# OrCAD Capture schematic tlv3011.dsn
size A
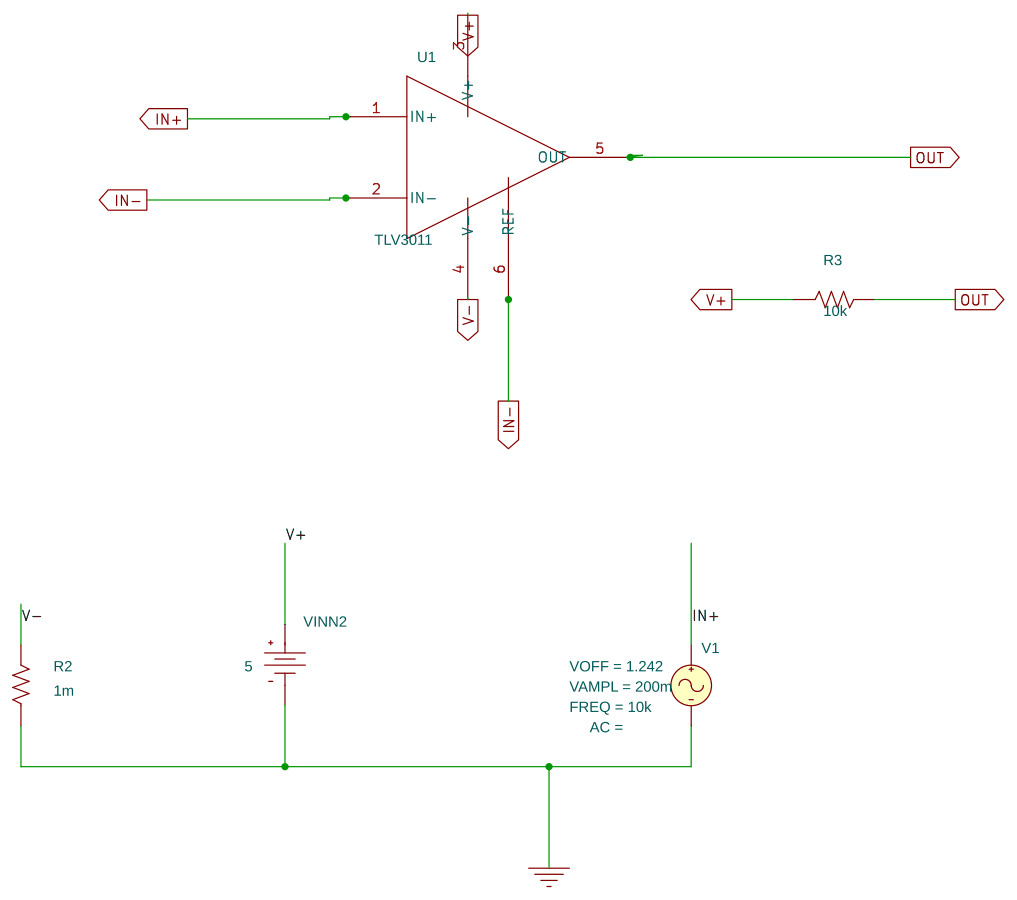
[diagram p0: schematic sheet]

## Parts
R2  1m  [AXRC05]
R3  10k  [AXRC05]
U1  TLV3011
V1  VSIN
VINN2  VDC

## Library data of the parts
R2 R3 = R
U1 = TLV3011_3
V1 = VSIN: FREQ: 10k; VAMPL: 200m; VOFF: 1.242
VINN2 = VDC: DC: 5

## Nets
0: R2.1 V1.2(-) VINN2.1(-)
IN+: U1.1(IN+) V1.1(+)
IN-: U1.2(IN-) U1.6(REF)
OUT: R3.2 U1.5(OUT)
V+: R3.1 U1.3(V+) VINN2.0(+)
V-: R2.2 U1.4(V-)
